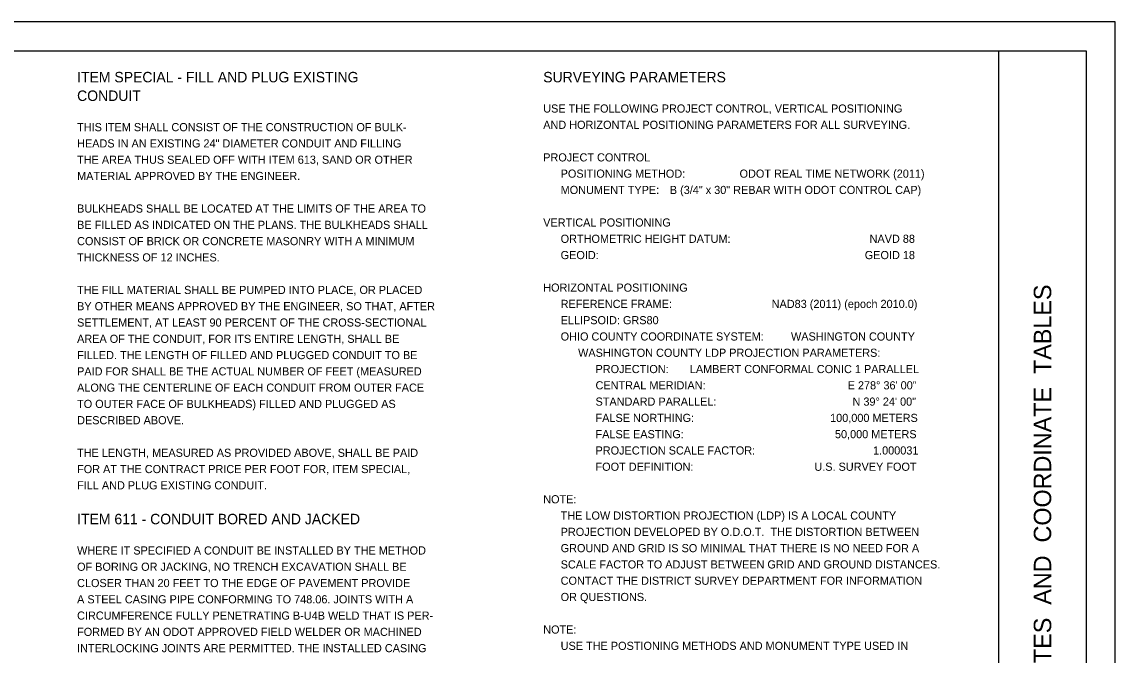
# Model space of a CAD drawing. Extents: x -30 to 76, y -31 to 50.
# Drawn here: x 15.19 to 34, y 11.11 to 22 of the extents above; entities that cross this region are included whole.
import ezdxf

# ---------------------------------------------------------------- set-up
doc = ezdxf.new("R2010")
doc.units = 0
for name, color, linetype in [('SH_Border', 7, 'Continuous'), ('SH_Cut_Line', 7, 'Continuous'), ('SH_Data', 7, 'Continuous'), ('SH_Text', 7, 'Continuous'), ('SV_X_Text', 7, 'Continuous')]:
    doc.layers.add(name, color=color, linetype=linetype)

msp = doc.modelspace()

# ---------------------------------------------------------------- linework, layer by layer
at = {"layer": 'SH_Border'}
msp.add_line((32, 0.5), (32, 21.5), dxfattribs=at)
msp.add_lwpolyline([(1.5, 21.5), (33.5, 21.5), (33.5, 0.5), (1.5, 0.5)], close=True, dxfattribs=at)
at = {"layer": 'SH_Cut_Line'}
msp.add_lwpolyline([(0, 0), (34, 0), (34, 22), (0, 22)], close=True, dxfattribs=at)

# ---------------------------------------------------------------- texts
at = {"layer": 'SH_Data'}
msp.add_text('GENERAL  NOTES  AND  COORDINATE  TABLES', height=0.3, rotation=90, dxfattribs=at).set_placement((32.9, 8.232))
at = {"layer": 'SH_Text'}
for s, height, p in [('ITEM SPECIAL - FILL AND PLUG EXISTING', 0.18, (16.14, 20.96)), ('SURVEYING PARAMETERS', 0.18, (24.16, 20.96)), ('CONDUIT', 0.18, (16.14, 20.64)), ('THIS ITEM SHALL CONSIST OF THE CONSTRUCTION OF BULK-', 0.14, (16.14, 20.12)), ('HEADS IN AN EXISTING 24" DIAMETER CONDUIT AND FILLING', 0.14, (16.14, 19.84)), ('THE AREA THUS SEALED OFF WITH ITEM 613, SAND OR OTHER', 0.14, (16.14, 19.56)), ('PROJECT CONTROL', 0.14, (24.16, 19.6)), ('MATERIAL APPROVED BY THE ENGINEER.', 0.14, (16.14, 19.28)), ('POSITIONING METHOD:   ', 0.14, (24.46, 19.32)), ('             ODOT REAL TIME NETWORK (2011)', 0.14, (26.862, 19.32)), (' B (3/4" x 30" REBAR WITH ODOT CONTROL CAP)', 0.14, (26.286, 19.04)), ('MONUMENT TYPE: ', 0.14, (24.46, 19.04)), ('BULKHEADS SHALL BE LOCATED AT THE LIMITS OF THE AREA TO', 0.14, (16.14, 18.72)), ('VERTICAL POSITIONING', 0.14, (24.16, 18.48)), ('BE FILLED AS INDICATED ON THE PLANS. THE BULKHEADS SHALL', 0.14, (16.14, 18.44)), ('CONSIST OF BRICK OR CONCRETE MASONRY WITH A MINIMUM', 0.14, (16.14, 18.16)), ('ORTHOMETRIC HEIGHT DATUM:                                              NAVD 88', 0.14, (24.46, 18.2)), ('GEOID:                                                                                        GEOID 18', 0.14, (24.46, 17.92)), ('THICKNESS OF 12 INCHES.', 0.14, (16.14, 17.88)), ('HORIZONTAL POSITIONING', 0.14, (24.16, 17.36)), ('THE FILL MATERIAL SHALL BE PUMPED INTO PLACE, OR PLACED', 0.14, (16.14, 17.32)), ('BY OTHER MEANS APPROVED BY THE ENGINEER, SO THAT, AFTER', 0.14, (16.14, 17.04)), ('SETTLEMENT, AT LEAST 90 PERCENT OF THE CROSS-SECTIONAL', 0.14, (16.14, 16.76)), ('AREA OF THE CONDUIT, FOR ITS ENTIRE LENGTH, SHALL BE', 0.14, (16.14, 16.48)), ('FILLED. THE LENGTH OF FILLED AND PLUGGED CONDUIT TO BE', 0.14, (16.14, 16.2)), ('PAID FOR SHALL BE THE ACTUAL NUMBER OF FEET (MEASURED', 0.14, (16.14, 15.92)), ('ALONG THE CENTERLINE OF EACH CONDUIT FROM OUTER FACE', 0.14, (16.14, 15.64)), ('TO OUTER FACE OF BULKHEADS) FILLED AND PLUGGED AS', 0.14, (16.14, 15.36)), ('DESCRIBED ABOVE.', 0.14, (16.14, 15.08)), ('THE LENGTH, MEASURED AS PROVIDED ABOVE, SHALL BE PAID', 0.14, (16.14, 14.52)), ('FOR AT THE CONTRACT PRICE PER FOOT FOR, ITEM SPECIAL,', 0.14, (16.14, 14.24)), ('FILL AND PLUG EXISTING CONDUIT.', 0.14, (16.14, 13.96)), ('NOTE:', 0.14, (24.16, 13.72)), ('ITEM 611 - CONDUIT BORED AND JACKED', 0.18, (16.14, 13.36)), ('WHERE IT SPECIFIED A CONDUIT BE INSTALLED BY THE METHOD', 0.14, (16.14, 12.84)), ('OF BORING OR JACKING, NO TRENCH EXCAVATION SHALL BE', 0.14, (16.14, 12.56)), ('CLOSER THAN 20 FEET TO THE EDGE OF PAVEMENT PROVIDE', 0.14, (16.14, 12.28)), ('A STEEL CASING PIPE CONFORMING TO 748.06. JOINTS WITH A', 0.14, (16.14, 12)), ('CIRCUMFERENCE FULLY PENETRATING B-U4B WELD THAT IS PER-', 0.14, (16.14, 11.72)), ('FORMED BY AN ODOT APPROVED FIELD WELDER OR MACHINED', 0.14, (16.14, 11.44)), ('NOTE:', 0.14, (24.16, 11.48)), ('INTERLOCKING JOINTS ARE PERMITTED. THE INSTALLED CASING', 0.14, (16.14, 11.16))]:
    msp.add_text(s, height=height, dxfattribs=at).set_placement(p)
at = {"layer": 'SV_X_Text'}
for s, p in [('USE THE FOLLOWING PROJECT CONTROL, VERTICAL POSITIONING', (24.16, 20.44)), ('AND HORIZONTAL POSITIONING PARAMETERS FOR ALL SURVEYING.', (24.16, 20.16)), ('REFERENCE FRAME:                                 NAD83 (2011) (epoch 2010.0)', (24.46, 17.08)), ('ELLIPSOID: GRS80', (24.46, 16.8)), ('OHIO COUNTY COORDINATE SYSTEM:         WASHINGTON COUNTY', (24.46, 16.52)), ('WASHINGTON COUNTY LDP PROJECTION PARAMETERS:', (24.76, 16.24)), ('PROJECTION:       LAMBERT CONFORMAL CONIC 1 PARALLEL', (25.06, 15.96)), ('CENTRAL MERIDIAN:                                               E 278%%D 36\' 00"', (25.06, 15.68)), ('STANDARD PARALLEL:                                             N 39%%D 24\' 00"', (25.06, 15.4)), ('FALSE NORTHING:                                             100,000 METERS', (25.06, 15.12)), ('FALSE EASTING:                                                  50,000 METERS', (25.06, 14.84)), ('PROJECTION SCALE FACTOR:                                       1.000031', (25.06, 14.56)), ('FOOT DEFINITION:                                        U.S. SURVEY FOOT', (25.06, 14.28)), ('THE LOW DISTORTION PROJECTION (LDP) IS A LOCAL COUNTY', (24.46, 13.44)), ('PROJECTION DEVELOPED BY O.D.O.T.  THE DISTORTION BETWEEN', (24.46, 13.16)), ('GROUND AND GRID IS SO MINIMAL THAT THERE IS NO NEED FOR A', (24.46, 12.88)), ('SCALE FACTOR TO ADJUST BETWEEN GRID AND GROUND DISTANCES.', (24.46, 12.6)), ('CONTACT THE DISTRICT SURVEY DEPARTMENT FOR INFORMATION', (24.46, 12.32)), ('OR QUESTIONS.', (24.46, 12.04)), ('USE THE POSTIONING METHODS AND MONUMENT TYPE USED IN', (24.46, 11.2))]:
    msp.add_text(s, height=0.14, dxfattribs=at).set_placement(p)

doc.saveas('drawing.dxf')
